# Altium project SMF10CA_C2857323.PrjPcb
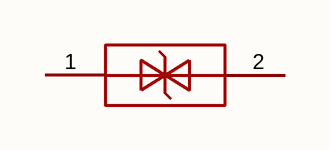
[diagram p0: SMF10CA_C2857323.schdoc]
1 sheet, 1 parts. Net scope: global (net labels, ports and power ports of the same name join across sheets).

## Sheet SMF10CA_C2857323.schdoc
size 127 x 101 mm

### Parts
U?  smf10ca_c2857323  [SOD-123FL_L2.9-W1.8-LS3.9-BI]  (value not drawn)

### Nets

Not connected (* = marked no-connect by the designer): U? 1 2

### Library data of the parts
U? = smf10ca_c2857323: 极性:双向;反向截止电压(Vrwm):10V;钳位电压:17V;峰值脉冲电流(Ipp):11.8A;峰值脉冲功率(Ppp):200W@10/1000us;击穿电压(VBR):12.3V;; Manufacturer: JSMSEMI(杰盛微); AddInBom: yes; ModelId: 95f4fe22ea1f495793d6c281dc321fca; ModelTransform: 153.543,70.866,0,0,0,0,-0.001,0,0; Polarity: 双向; Reverse Stand-Off Voltage (Vrwm): 10V; Clamping Voltage: 17V; Peak Pulse Current (Ipp): 11.8A; Voltage - Breakdown: 12.3V; Reverse Leakage Current (Ir): 2.5uA; Number of Channels: 单路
